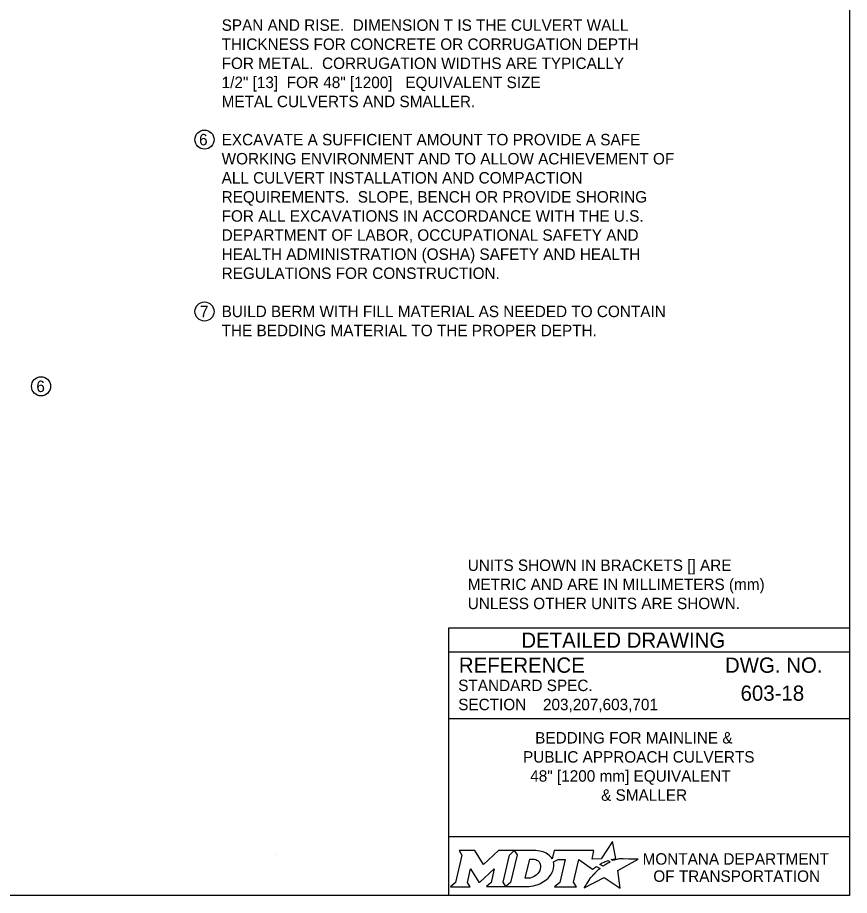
# Model space of a CAD drawing. Extents: x 49991.4 to 50021, y 49987.6 to 50011.4.
# Drawn here: x 50012.392 to 50016.75, y 49987.799 to 49992.398 of the extents above; entities that cross this region are included whole.
import ezdxf

# ---------------------------------------------------------------- set-up
doc = ezdxf.new("R2010")
doc.units = 0
for name, color, linetype in [('Default', 7, 'Continuous'), ('Level 1', 7, 'Continuous'), ('Level 2', 7, 'Continuous'), ('Level 5', 7, 'Continuous')]:
    doc.layers.add(name, color=color, linetype=linetype)

msp = doc.modelspace()

# ---------------------------------------------------------------- linework, layer by layer
at = {"layer": 'Default'}
for points in [[(50015.5126, 49987.9811), (50015.5023, 49987.9867), (50015.5139, 49987.9895), (50015.5255, 49987.9915), (50015.5081, 49988.0816), (50015.4486, 49987.9903), (50015.4013, 49987.9896), (50015.4116, 49988.0337), (50015.2024, 49988.0338), (50015.1923, 49987.9913), (50015.1865, 49987.9996)], [(50014.7056, 49988.0338), (50014.7197, 49988.0104), (50014.6862, 49987.8671), (50014.6605, 49987.8446), (50014.7621, 49987.8446), (50014.7486, 49987.8674), (50014.7648, 49987.9375), (50014.8085, 49987.8685), (50014.8138, 49987.8685), (50014.8889, 49987.938), (50014.8725, 49987.8669), (50014.8478, 49987.8449), (50014.9494, 49987.8449), (50014.9356, 49987.8682), (50014.9688, 49988.0106)], [(50014.9688, 49988.0106), (50014.9941, 49988.0338), (50014.9117, 49988.0338), (50014.8321, 49987.9608), (50014.7876, 49988.0335), (50014.7056, 49988.0338)], [(50015.1077, 49988.0338), (50014.9941, 49988.0338), (50015.0088, 49988.0109), (50014.9749, 49987.8671), (50014.9494, 49987.8449), (50015.06, 49987.8449)], [(50015.1317, 49987.9471), (50015.1305, 49987.939), (50015.1273, 49987.9297), (50015.1231, 49987.9215), (50015.1175, 49987.914), (50015.111, 49987.9071), (50015.1031, 49987.9008), (50015.0948, 49987.8961), (50015.0857, 49987.8922), (50015.0766, 49987.8899), (50015.0674, 49987.889), (50015.0515, 49987.889), (50015.0751, 49987.989), (50015.0911, 49987.989), (50015.0987, 49987.9884), (50015.1063, 49987.9865), (50015.1129, 49987.9835), (50015.119, 49987.9793), (50015.1238, 49987.9743), (50015.1275, 49987.9683), (50015.1302, 49987.9621), (50015.1318, 49987.9547), (50015.1318, 49987.9517), (50015.1317, 49987.9471)], [(50015.1991, 49987.9747), (50015.2237, 49987.9878), (50015.2606, 49987.9878), (50015.232, 49987.8673), (50015.2045, 49987.8446), (50015.3207, 49987.8446), (50015.3037, 49987.8675), (50015.3319, 49987.9877), (50015.4032, 49987.936), (50015.4243, 49987.9511), (50015.444, 49987.9402)], [(50015.3882, 49987.8843), (50015.3729, 49987.8599), (50015.3682, 49987.8524), (50015.3624, 49987.8438), (50015.3601, 49987.8395), (50015.4654, 49987.8926), (50015.5493, 49987.8375), (50015.5362, 49987.9302), (50015.6431, 49987.9886), (50015.5938, 49987.9894), (50015.5637, 49987.9898), (50015.5429, 49987.9901), (50015.5361, 49987.9886), (50015.5312, 49987.9874), (50015.5228, 49987.9851), (50015.5126, 49987.9811)], [(50015.4622, 49987.9535), (50015.4598, 49987.9518), (50015.4415, 49987.9614), (50015.4518, 49987.9671), (50015.4559, 49987.9693), (50015.4645, 49987.9733), (50015.4702, 49987.9759), (50015.4781, 49987.9789), (50015.4854, 49987.9816), (50015.4972, 49987.9742), (50015.4932, 49987.9721), (50015.4886, 49987.9696), (50015.4844, 49987.9674), (50015.4794, 49987.9645), (50015.4775, 49987.9634), (50015.4748, 49987.9618), (50015.4723, 49987.9604), (50015.47, 49987.9588), (50015.4674, 49987.957), (50015.4647, 49987.9552), (50015.4622, 49987.9535)], [(50015.4021, 49987.9004), (50015.4021, 49987.9004)], [(50015.1057, 49987.8522), (50015.1141, 49987.8548), (50015.1271, 49987.8602), (50015.1475, 49987.8712)]]:
    msp.add_lwpolyline(points, dxfattribs=at)
for centre, radius, start, end in [((50015.1308, 49987.9554), 0.0709, 339.5329, 15.8582), ((50015.0868, 49987.9727), 0.1183, 300.9103, 339.1383)]:
    msp.add_arc(centre, radius, start, end, dxfattribs=at)
for centre, major_axis, ratio, start_param, end_param in [((50015.1056, 49987.9864), (0.0834, -0.0037), 0.568097, 0.61298, 1.570796), ((50015.1612, 49987.9937), (0.0361, -0.0295), 0.469099, 1.225588, 1.570796), ((50015.4329, 49987.9305), (-0.0112, -0.0097), 0.021651, 3.157348, 6.283185), ((50015.3952, 49987.8923), (-0.00694, -0.00806), 0.008222, 0, 3.137361), ((50015.4119, 49987.9106), (-0.0098, -0.0102), 0.016458, 3.141593, 6.279097), ((50015.0603, 49987.9932), (0, 0.1484), 0.987302, 3.139398, 3.456847)]:
    msp.add_ellipse(centre, major_axis=major_axis, ratio=ratio, start_param=start_param, end_param=end_param, dxfattribs=at)
at = {"layer": 'Level 1'}
msp.add_lwpolyline([(49999.3835, 49998.9992), (50016.7501, 49998.9992), (50016.7501, 49987.7988), (49999.3835, 49987.7988)], close=True, dxfattribs=at)
at = {"layer": 'Level 2'}
msp.add_line((50013.7461, 49988.0122), (50013.7461, 49988.0122), dxfattribs=at)
for centre in [(50013.3708, 49991.7587), (50013.3709, 49990.8584), (50012.5145, 49990.4662)]:
    msp.add_circle(centre, 0.05, dxfattribs=at)
at = {"layer": 'Level 5'}
for p, q in [((50016.7501, 49989.1988), (50014.6501, 49989.1988)), ((50014.6501, 49989.1988), (50014.6501, 49987.7988)), ((50016.7501, 49989.0738), (50014.6501, 49989.0738)), ((50016.3862, 49988.8587), (50016.3862, 49988.8587)), ((50015.1444, 49988.7993), (50015.1444, 49988.7993)), ((50016.7501, 49988.7238), (50014.6501, 49988.7238)), ((50015.7001, 49988.4747), (50015.7001, 49988.4747)), ((50016.7501, 49988.1057), (50014.6501, 49988.1057))]:
    msp.add_line(p, q, dxfattribs=at)

# ---------------------------------------------------------------- texts
at = {"layer": 'Default'}
for s, p in [('MONTANA DEPARTMENT', (50015.6663, 49987.96)), ('OF TRANSPORTATION', (50015.7225, 49987.87))]:
    msp.add_text(s, height=0.06, dxfattribs=at).set_placement(p)
at = {"layer": 'Level 2'}
for s, height, p in [('SPAN AND RISE.  DIMENSION T IS THE CULVERT WALL', 0.06, (50013.4608, 49992.3287)), ('THICKNESS FOR CONCRETE OR CORRUGATION DEPTH', 0.06, (50013.4608, 49992.2287)), ('FOR METAL.  CORRUGATION WIDTHS ARE TYPICALLY  ', 0.06, (50013.4608, 49992.1287)), ('1/2" [13]  FOR 48" [1200]   EQUIVALENT SIZE', 0.06, (50013.4608, 49992.0287)), ('METAL CULVERTS AND SMALLER.', 0.06, (50013.4608, 49991.9287)), ('6', 0.06, (50013.3426, 49991.7287)), ('EXCAVATE A SUFFICIENT AMOUNT TO PROVIDE A SAFE', 0.06, (50013.4608, 49991.7287)), ('WORKING ENVIRONMENT AND TO ALLOW ACHIEVEMENT OF', 0.06, (50013.4608, 49991.6287)), ('ALL CULVERT INSTALLATION AND COMPACTION', 0.06, (50013.4608, 49991.5287)), ('REQUIREMENTS.  SLOPE, BENCH OR PROVIDE SHORING', 0.06, (50013.4608, 49991.4287)), ('FOR ALL EXCAVATIONS IN ACCORDANCE WITH THE U.S.', 0.06, (50013.4608, 49991.3287)), ('DEPARTMENT OF LABOR, OCCUPATIONAL SAFETY AND', 0.06, (50013.4608, 49991.2287)), ('HEALTH ADMINISTRATION (OSHA) SAFETY AND HEALTH', 0.06, (50013.4608, 49991.1287)), ('REGULATIONS FOR CONSTRUCTION.', 0.06, (50013.4608, 49991.0287)), ('7', 0.06, (50013.3471, 49990.8284)), ('BUILD BERM WITH FILL MATERIAL AS NEEDED TO CONTAIN', 0.06, (50013.4608, 49990.8287)), ('THE BEDDING MATERIAL TO THE PROPER DEPTH.', 0.06, (50013.4608, 49990.7287)), ('6', 0.06, (50012.49, 49990.4362)), ('UNITS SHOWN IN BRACKETS [] ARE ', 0.06, (50014.7501, 49989.4988)), ('METRIC AND ARE IN MILLIMETERS (mm) ', 0.06, (50014.7501, 49989.3988)), ('UNLESS OTHER UNITS ARE SHOWN.', 0.06, (50014.7501, 49989.2988)), ('603-18', 0.08, (50016.1797, 49988.8187)), ('203,207,603,701', 0.06, (50015.1444, 49988.7693)), ('BEDDING FOR MAINLINE &', 0.06, (50015.1035, 49988.5947)), ('PUBLIC APPROACH CULVERTS', 0.06, (50015.0399, 49988.4947)), ('48" [1200 mm] EQUIVALENT ', 0.06, (50015.0776, 49988.3947)), ('& SMALLER', 0.06, (50015.4492, 49988.2947))]:
    msp.add_text(s, height=height, dxfattribs=at).set_placement(p)
at = {"layer": 'Level 5'}
for s, height, p in [('DETAILED DRAWING', 0.0799, (50015.0311, 49989.0963)), ('REFERENCE', 0.08, (50014.7037, 49988.9654)), ('DWG. NO.', 0.08, (50016.0979, 49988.9654)), ('STANDARD SPEC.', 0.06, (50014.7004, 49988.8694)), ('SECTION', 0.06, (50014.7004, 49988.7694))]:
    msp.add_text(s, height=height, dxfattribs=at).set_placement(p)

doc.saveas('drawing.dxf')
